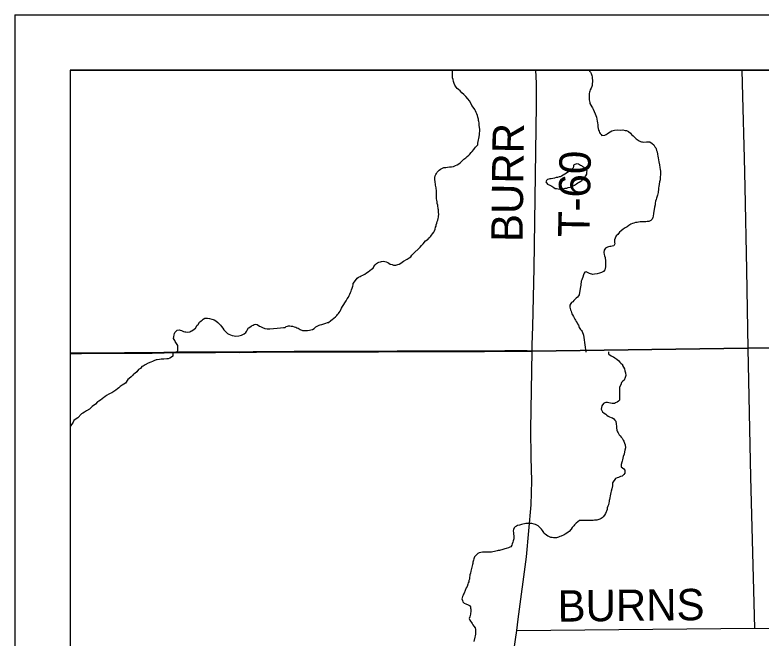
# Model space of a CAD drawing. Extents: x 0 to 34, y 0 to 22.
# Drawn here: x 2 to 3.351, y 19.872 to 21 of the extents above; entities that cross this region are included whole.
import ezdxf

# ---------------------------------------------------------------- set-up
doc = ezdxf.new("R2010")
doc.units = 0
for name, color, linetype in [('GM_X_Corporation', 7, 'Continuous'), ('GM_X_County_Road', 7, 'Continuous'), ('GM_X_Minor_Lake', 7, 'Continuous'), ('GM_X_Minor_River', 7, 'Continuous'), ('GM_X_Township_Road', 7, 'Continuous'), ('GM_X_Township_Road_Text', 7, 'Continuous'), ('SH_Data', 7, 'Continuous')]:
    doc.layers.add(name, color=color, linetype=linetype)

msp = doc.modelspace()

# ---------------------------------------------------------------- linework, layer by layer
at = {"layer": 'GM_X_Corporation'}
for points in [[(6.9799, 20.9), (2.1, 20.9), (2.1, 20.3879), (2.1205, 20.3882), (2.1982, 20.3886), (2.2479, 20.3887), (2.2915, 20.3895), (2.3257, 20.3896), (2.363, 20.39), (2.3847, 20.39), (2.4065, 20.39), (2.4312, 20.3904), (2.4374, 20.3905), (2.4684, 20.3906), (2.5057, 20.3907), (2.515, 20.3907), (2.5336, 20.3908), (2.5492, 20.3908), (2.5709, 20.3908), (2.5926, 20.3909), (2.6268, 20.391), (2.6578, 20.3911), (2.6919, 20.3913), (2.7071, 20.3914), (2.7505, 20.3915), (2.7629, 20.3915), (2.8126, 20.3916), (2.8375, 20.3917), (2.8499, 20.3918), (2.8623, 20.3918), (2.887, 20.3922), (2.9019, 20.3922), (2.9179, 20.3921), (2.9272, 20.392), (2.9362, 20.3918), (3.3271, 20.397), (4.0334, 20.4012)], [(6.9799, 20.9), (2.1, 20.9), (2.1, 20.3879), (2.1205, 20.3882), (2.1982, 20.3886), (2.2479, 20.3887), (2.2915, 20.3895), (2.3257, 20.3896), (2.363, 20.39), (2.3847, 20.39), (2.4065, 20.39), (2.4312, 20.3904), (2.4374, 20.3905), (2.4684, 20.3906), (2.5057, 20.3907), (2.515, 20.3907), (2.5336, 20.3908), (2.5492, 20.3908), (2.5709, 20.3908), (2.5926, 20.3909), (2.6268, 20.391), (2.6578, 20.3911), (2.6919, 20.3913), (2.7071, 20.3914), (2.7505, 20.3915), (2.7629, 20.3915), (2.8126, 20.3916), (2.8375, 20.3917), (2.8499, 20.3918), (2.8623, 20.3918), (2.887, 20.3922), (2.9019, 20.3922), (2.9179, 20.3921), (2.9272, 20.392), (2.9362, 20.3918), (3.3271, 20.397), (4.0334, 20.4012)], [(4.0334, 20.4012), (3.3271, 20.397), (2.9362, 20.3918), (2.9272, 20.392), (2.9179, 20.3921), (2.9019, 20.3922), (2.887, 20.3922), (2.8623, 20.3918), (2.8499, 20.3918), (2.8375, 20.3917), (2.8126, 20.3916), (2.7629, 20.3915), (2.7505, 20.3915), (2.7071, 20.3914), (2.6919, 20.3913), (2.6578, 20.3911), (2.6268, 20.391), (2.5926, 20.3909), (2.5709, 20.3908), (2.5492, 20.3908), (2.5336, 20.3908), (2.515, 20.3907), (2.5057, 20.3907), (2.4684, 20.3906), (2.4374, 20.3905), (2.4312, 20.3904), (2.4065, 20.39), (2.3847, 20.39), (2.363, 20.39), (2.3257, 20.3896), (2.2915, 20.3895), (2.2479, 20.3887), (2.1982, 20.3886), (2.1205, 20.3882), (2.1, 20.3879), (2.1, 14.1)], [(4.0334, 20.4012), (3.3271, 20.397), (2.9362, 20.3918), (2.9272, 20.392), (2.9179, 20.3921), (2.9019, 20.3922), (2.887, 20.3922), (2.8623, 20.3918), (2.8499, 20.3918), (2.8375, 20.3917), (2.8126, 20.3916), (2.7629, 20.3915), (2.7505, 20.3915), (2.7071, 20.3914), (2.6919, 20.3913), (2.6578, 20.3911), (2.6268, 20.391), (2.5926, 20.3909), (2.5709, 20.3908), (2.5492, 20.3908), (2.5336, 20.3908), (2.515, 20.3907), (2.5057, 20.3907), (2.4684, 20.3906), (2.4374, 20.3905), (2.4312, 20.3904), (2.4065, 20.39), (2.3847, 20.39), (2.363, 20.39), (2.3257, 20.3896), (2.2915, 20.3895), (2.2479, 20.3887), (2.1982, 20.3886), (2.1205, 20.3882), (2.1, 20.3879), (2.1, 15.3574)]]:
    msp.add_lwpolyline(points, dxfattribs=at)
at = {"layer": 'GM_X_County_Road'}
msp.add_lwpolyline([(3.3273, 20.3964), (3.3254, 20.5388), (3.322, 20.6881), (3.3208, 20.7409), (3.318, 20.8528), (3.3167, 20.9)], dxfattribs=at)
at = {"layer": 'GM_X_Minor_Lake'}
for points in [[(2.9643, 20.6937), (2.9685, 20.6918), (2.9719, 20.69), (2.9754, 20.6877), (2.9784, 20.6862), (2.9807, 20.6859), (2.9834, 20.6851), (2.9868, 20.6848), (2.9898, 20.6848), (2.9921, 20.6852), (2.9963, 20.6864), (2.999, 20.6868), (3.0016, 20.6876), (3.0054, 20.6884), (3.0077, 20.6892), (3.0103, 20.6908), (3.013, 20.6919), (3.0167, 20.6946), (3.0194, 20.6962), (3.0217, 20.6973), (3.0243, 20.6989), (3.0262, 20.7004), (3.0303, 20.7043), (3.0318, 20.7062), (3.0337, 20.7089), (3.0352, 20.7116), (3.0355, 20.7154), (3.0359, 20.718), (3.0344, 20.7199), (3.032, 20.7226), (3.0301, 20.7237), (3.0282, 20.7252), (3.0263, 20.7267), (3.024, 20.7278), (3.0221, 20.7289), (3.0202, 20.7301), (3.0175, 20.7304), (3.0156, 20.73), (3.0137, 20.7292), (3.0115, 20.7281), (3.0111, 20.7258), (3.0104, 20.7231), (3.0085, 20.7212), (3.0058, 20.7192), (3.0036, 20.7166), (3.0013, 20.7154), (2.9988, 20.7134)], [(2.9988, 20.7134), (2.9896, 20.7084), (2.987, 20.7073), (2.9851, 20.7069), (2.9824, 20.7061), (2.9798, 20.7057), (2.9771, 20.7049), (2.9737, 20.7041), (2.9707, 20.7037), (2.9684, 20.7033), (2.9665, 20.7029), (2.9642, 20.7025), (2.9623, 20.7005), (2.9612, 20.6979), (2.9643, 20.6937)]]:
    msp.add_lwpolyline(points, dxfattribs=at)
at = {"layer": 'GM_X_Minor_River'}
msp.add_line((2.7923, 20.8997), (2.7923, 20.9), dxfattribs=at)
for points in [[(2.7668, 20.6338), (2.7668, 20.6361), (2.7672, 20.6391), (2.7671, 20.6429), (2.7667, 20.6452), (2.7667, 20.6471), (2.7663, 20.649), (2.7663, 20.6509), (2.7659, 20.6532), (2.7655, 20.6559), (2.7647, 20.6589), (2.7643, 20.6619), (2.7639, 20.6646), (2.7635, 20.6672), (2.7634, 20.6707), (2.7634, 20.6737), (2.7634, 20.6768), (2.7633, 20.6798), (2.7633, 20.6828), (2.7629, 20.6851), (2.7625, 20.6874), (2.7621, 20.6893), (2.7617, 20.692), (2.7613, 20.6942), (2.7609, 20.6969), (2.7601, 20.7034), (2.7604, 20.706), (2.7608, 20.7087), (2.7619, 20.7114), (2.763, 20.7133), (2.7645, 20.7152), (2.766, 20.7175), (2.7679, 20.719), (2.7705, 20.721), (2.7743, 20.7229), (2.7766, 20.7237), (2.78, 20.7241), (2.7834, 20.7245), (2.7868, 20.725), (2.7906, 20.7254), (2.7941, 20.7258), (2.7978, 20.7274), (2.8005, 20.7289), (2.8035, 20.7308), (2.8065, 20.7331), (2.8095, 20.7358), (2.8129, 20.7389), (2.8163, 20.7416), (2.819, 20.7439), (2.8216, 20.7462), (2.8235, 20.7478), (2.8261, 20.7512), (2.828, 20.7528), (2.8306, 20.7562), (2.8321, 20.7585), (2.834, 20.7608), (2.8355, 20.7628), (2.8378, 20.7651), (2.8381, 20.7677), (2.8385, 20.7712), (2.8392, 20.7742), (2.8399, 20.7761), (2.8414, 20.783), (2.8413, 20.786), (2.8417, 20.7895), (2.8417, 20.7925), (2.8412, 20.7967), (2.8408, 20.7997), (2.8404, 20.8024), (2.8404, 20.805), (2.84, 20.8073), (2.8396, 20.8092), (2.8392, 20.8111), (2.838, 20.8153), (2.8376, 20.8183), (2.8364, 20.821), (2.8353, 20.8236), (2.8337, 20.8267), (2.8326, 20.8289), (2.8298, 20.8331), (2.8275, 20.8361), (2.8252, 20.8403), (2.8229, 20.8444), (2.8198, 20.8482), (2.8164, 20.8524), (2.8129, 20.8561), (2.8094, 20.8591), (2.806, 20.8629), (2.8029, 20.8652), (2.8006, 20.867), (2.7991, 20.8693), (2.7964, 20.8731), (2.7952, 20.8761), (2.794, 20.8795), (2.7932, 20.8829), (2.7924, 20.886), (2.7924, 20.8886), (2.792, 20.8909), (2.7924, 20.8936), (2.7923, 20.8962), (2.7923, 20.8997)], [(3.0394, 20.9), (3.0405, 20.8985), (3.0421, 20.8966), (3.0432, 20.8943), (3.0444, 20.8905), (3.0448, 20.8878), (3.0452, 20.8848), (3.0457, 20.8818), (3.0457, 20.8787), (3.0453, 20.8761), (3.045, 20.8726), (3.0442, 20.8703), (3.0431, 20.8677), (3.0416, 20.8646), (3.0409, 20.8623), (3.0402, 20.86), (3.0394, 20.8577), (3.0395, 20.8554), (3.0395, 20.8528), (3.0395, 20.8494), (3.0399, 20.8463), (3.0403, 20.844), (3.0407, 20.8418), (3.0411, 20.8395), (3.0427, 20.8365), (3.0446, 20.8338), (3.0454, 20.8319), (3.0466, 20.8293), (3.0504, 20.8209), (3.052, 20.8179), (3.0528, 20.8149), (3.0536, 20.8111), (3.054, 20.808), (3.0548, 20.8046), (3.0552, 20.8012), (3.0556, 20.7978), (3.056, 20.7947), (3.0568, 20.7917), (3.0576, 20.7894), (3.0584, 20.7875), (3.0595, 20.7856), (3.0611, 20.7838), (3.0626, 20.7819), (3.0679, 20.7823), (3.0702, 20.7838), (3.0721, 20.785), (3.0747, 20.7869), (3.0774, 20.7885), (3.0804, 20.79), (3.0857, 20.7916), (3.0903, 20.792)], [(3.0903, 20.792), (3.0956, 20.7917), (3.1005, 20.7918), (3.1047, 20.7911), (3.1074, 20.7907), (3.1108, 20.7892), (3.1143, 20.7862), (3.1166, 20.7836), (3.1196, 20.7813), (3.1212, 20.7794), (3.125, 20.776), (3.1281, 20.7734), (3.13, 20.7723), (3.1323, 20.7712), (3.1342, 20.7704), (3.1361, 20.7701), (3.1384, 20.7697), (3.1433, 20.7702), (3.1456, 20.7706), (3.1475, 20.7702), (3.1494, 20.7702), (3.1536, 20.7676), (3.1567, 20.765), (3.1586, 20.7616), (3.1602, 20.7593), (3.1609, 20.7574), (3.1617, 20.7547), (3.1625, 20.7521), (3.1633, 20.7479), (3.1641, 20.7445), (3.1645, 20.7415), (3.1653, 20.738), (3.1657, 20.7339), (3.1669, 20.7285), (3.1677, 20.724), (3.1685, 20.7202), (3.1689, 20.7171), (3.169, 20.7145), (3.1686, 20.7111), (3.1683, 20.7065), (3.168, 20.7019), (3.1672, 20.6977), (3.1665, 20.6935), (3.1658, 20.6897), (3.1654, 20.687), (3.1651, 20.6836), (3.1648, 20.6806), (3.1644, 20.6787), (3.164, 20.6764), (3.1633, 20.6737), (3.1626, 20.6718), (3.1618, 20.6687), (3.1607, 20.6661), (3.16, 20.663), (3.1593, 20.6596), (3.1589, 20.6562), (3.1582, 20.652), (3.1564, 20.6405), (3.1557, 20.636), (3.155, 20.6337), (3.1535, 20.6306), (3.1516, 20.6283), (3.1478, 20.6264), (3.1448, 20.6263), (3.1425, 20.6259), (3.1398, 20.6259), (3.1372, 20.6259), (3.1345, 20.6258), (3.1322, 20.6254), (3.1292, 20.625), (3.1265, 20.6246), (3.1235, 20.6242), (3.1205, 20.623), (3.1182, 20.6226), (3.1152, 20.6215), (3.1114, 20.6187), (3.1084, 20.6164), (3.105, 20.6145), (3.1012, 20.6122), (3.0974, 20.6095), (3.0944, 20.6068), (3.0914, 20.6029), (3.0888, 20.6002), (3.0865, 20.596), (3.0858, 20.593), (3.0854, 20.5903), (3.0855, 20.588), (3.0863, 20.5858), (3.0844, 20.5819), (3.0814, 20.5815), (3.0791, 20.5811), (3.0772, 20.5807), (3.0745, 20.5803), (3.0726, 20.5799), (3.0692, 20.578), (3.0666, 20.5741), (3.0663, 20.5699), (3.0667, 20.5665), (3.0675, 20.5643), (3.0686, 20.5612), (3.0687, 20.5593)], [(2.5298, 20.4289), (2.5332, 20.4293), (2.5359, 20.4301), (2.5389, 20.4305), (2.5415, 20.4328), (2.5449, 20.4355), (2.5472, 20.4371), (2.5506, 20.4386), (2.5525, 20.439), (2.5555, 20.4398), (2.5593, 20.441), (2.5631, 20.4425), (2.5658, 20.4433), (2.5677, 20.4437), (2.5718, 20.4468), (2.5744, 20.4491), (2.5771, 20.4514), (2.5801, 20.4538), (2.5827, 20.4561), (2.5842, 20.458), (2.5857, 20.4599), (2.5872, 20.4618), (2.5887, 20.4641), (2.5902, 20.4664), (2.5913, 20.4691), (2.5932, 20.4725), (2.5955, 20.476), (2.5973, 20.4791), (2.5996, 20.4825), (2.6018, 20.4863), (2.6037, 20.4894), (2.6052, 20.4925), (2.6063, 20.4947), (2.6074, 20.4978), (2.6089, 20.5001), (2.6096, 20.5024), (2.6107, 20.5058), (2.6115, 20.5093), (2.6122, 20.5119), (2.6126, 20.5138), (2.6182, 20.5219), (2.6197, 20.5238), (2.6223, 20.5257), (2.625, 20.5265), (2.6269, 20.5277), (2.6299, 20.5292), (2.6333, 20.5312), (2.6363, 20.5331), (2.6397, 20.5354), (2.6424, 20.5374), (2.6454, 20.5397), (2.6484, 20.542), (2.6499, 20.5447), (2.6521, 20.5477), (2.6544, 20.55), (2.6567, 20.5516), (2.6589, 20.5528), (2.6616, 20.5535), (2.6639, 20.554), (2.6669, 20.5544), (2.6696, 20.554), (2.6722, 20.5533), (2.6749, 20.5518), (2.6768, 20.5507), (2.6795, 20.5492), (2.6829, 20.5481), (2.6852, 20.5473), (2.6871, 20.5473), (2.6894, 20.5474), (2.6932, 20.5486), (2.6958, 20.5493), (2.6989, 20.5509), (2.7038, 20.5544), (2.7102, 20.5582), (2.714, 20.5602), (2.7166, 20.5625), (2.7185, 20.5652), (2.7211, 20.5675), (2.723, 20.5698), (2.7313, 20.5771), (2.7336, 20.5798), (2.7362, 20.5825), (2.7392, 20.5856), (2.7433, 20.5913), (2.7479, 20.594), (2.7486, 20.5959), (2.7512, 20.5979), (2.7531, 20.5994), (2.7542, 20.6013), (2.7561, 20.604), (2.7584, 20.6071), (2.7595, 20.6094), (2.7606, 20.6124), (2.7613, 20.6159), (2.7624, 20.6178), (2.7628, 20.6204), (2.7639, 20.6231), (2.7646, 20.6262), (2.7658, 20.6288), (2.7665, 20.6315), (2.7668, 20.6338)], [(3.0687, 20.5593), (3.0691, 20.5563), (3.0691, 20.5521), (3.0691, 20.5479), (3.0692, 20.5441), (3.0688, 20.5411), (3.0681, 20.5388), (3.0655, 20.5357), (3.0621, 20.5338), (3.0583, 20.5326), (3.0541, 20.5314), (3.0495, 20.531), (3.0465, 20.5305), (3.0442, 20.5309), (3.0423, 20.5313), (3.0404, 20.5324), (3.0366, 20.5342), (3.0343, 20.535), (3.0316, 20.5346), (3.0309, 20.5327), (3.0294, 20.5296), (3.0279, 20.5254), (3.0268, 20.5227), (3.0261, 20.5204), (3.0253, 20.5185), (3.025, 20.5162), (3.0246, 20.5136), (3.0243, 20.5113), (3.0239, 20.5079), (3.0221, 20.4979), (3.0214, 20.4938), (3.0203, 20.4918), (3.0184, 20.4892), (3.0162, 20.4872), (3.0139, 20.4853), (3.0116, 20.483), (3.0098, 20.4811), (3.0079, 20.4795), (3.0064, 20.4776), (3.0045, 20.4746), (3.0045, 20.4711), (3.0057, 20.4662), (3.0069, 20.4639), (3.0077, 20.4616), (3.0085, 20.4594), (3.0096, 20.4571), (3.0112, 20.4541), (3.0123, 20.4518), (3.0135, 20.4495), (3.015, 20.4476), (3.0162, 20.4454), (3.0181, 20.4427), (3.0185, 20.4408), (3.0201, 20.4389), (3.0216, 20.4344), (3.0239, 20.431), (3.0259, 20.4291), (3.027, 20.4272), (3.0294, 20.4204), (3.0302, 20.4166), (3.0337, 20.3899)], [(2.2945, 20.3879), (2.2952, 20.3956), (2.2952, 20.399), (2.2948, 20.4017), (2.294, 20.4036), (2.2913, 20.407), (2.2901, 20.4089), (2.2893, 20.4108), (2.2874, 20.4146), (2.2878, 20.4176), (2.2881, 20.421), (2.2892, 20.4233), (2.2896, 20.4252), (2.2918, 20.4279), (2.2937, 20.4295), (2.2971, 20.4299), (2.299, 20.4295), (2.3017, 20.4288), (2.3055, 20.4273), (2.3074, 20.4266), (2.3093, 20.4266), (2.312, 20.4262), (2.3166, 20.4267), (2.3184, 20.4278), (2.3203, 20.4282), (2.3245, 20.4313), (2.3268, 20.4329), (2.3301, 20.4386), (2.332, 20.4401), (2.3342, 20.4443), (2.3369, 20.4463), (2.3388, 20.4474), (2.341, 20.4494), (2.3437, 20.4513), (2.3486, 20.4513), (2.3524, 20.4506), (2.3566, 20.4495), (2.3589, 20.4488), (2.3608, 20.448), (2.3639, 20.4466), (2.3673, 20.4432), (2.3696, 20.4413), (2.3719, 20.4386), (2.3742, 20.436), (2.3766, 20.4334), (2.3785, 20.4303), (2.38, 20.4285), (2.3831, 20.4251), (2.385, 20.4236), (2.3873, 20.4224), (2.39, 20.4213), (2.3934, 20.4202), (2.3968, 20.4191), (2.3995, 20.4188), (2.4056, 20.4192), (2.4079, 20.42), (2.4105, 20.4208), (2.4124, 20.4216), (2.415, 20.4231), (2.4181, 20.4254), (2.4192, 20.4273), (2.4207, 20.4296), (2.4229, 20.4335), (2.4248, 20.4346), (2.4282, 20.4373), (2.4312, 20.4389), (2.4331, 20.4397), (2.4354, 20.4405), (2.4388, 20.4397), (2.4427, 20.4371), (2.4446, 20.436), (2.448, 20.4341), (2.4522, 20.4323), (2.4564, 20.4319), (2.4617, 20.432), (2.4682, 20.4324), (2.4746, 20.4329), (2.4807, 20.4337), (2.486, 20.4341), (2.4891, 20.4345), (2.4909, 20.4361), (2.4936, 20.4369), (2.4955, 20.4373), (2.4978, 20.4373), (2.5001, 20.4369), (2.5027, 20.4366), (2.5058, 20.4359), (2.5084, 20.4347), (2.5104, 20.434), (2.5126, 20.4329), (2.5146, 20.4321), (2.5165, 20.431), (2.5207, 20.4292), (2.5233, 20.4288), (2.5267, 20.4288), (2.5298, 20.4289)], [(2.2859, 20.3879), (2.2859, 20.3825), (2.2836, 20.381), (2.2802, 20.3787), (2.2775, 20.3779), (2.2748, 20.3776), (2.2695, 20.3772), (2.2672, 20.3768), (2.2646, 20.3768), (2.2615, 20.3764), (2.2577, 20.3757), (2.2558, 20.3757), (2.2517, 20.3738), (2.249, 20.373), (2.246, 20.3715), (2.241, 20.37), (2.2357, 20.3666), (2.2319, 20.3643), (2.2296, 20.3639), (2.2273, 20.3605), (2.2239, 20.3582), (2.2209, 20.3544), (2.2171, 20.351), (2.2144, 20.3502), (2.2136, 20.3479), (2.2102, 20.3449), (2.2068, 20.3422), (2.2045, 20.3404), (2.1999, 20.3335), (2.1942, 20.3301), (2.1908, 20.3278), (2.1882, 20.3255), (2.1859, 20.3236), (2.1828, 20.321), (2.179, 20.3183), (2.1756, 20.3164), (2.1726, 20.3149), (2.1703, 20.3138), (2.1661, 20.3111), (2.1627, 20.3092), (2.1608, 20.3077), (2.1581, 20.3054), (2.1551, 20.3031), (2.152, 20.3008), (2.1494, 20.2997), (2.1456, 20.2955), (2.1399, 20.2913), (2.1349, 20.2868), (2.1296, 20.2837), (2.1258, 20.2811), (2.1227, 20.2796), (2.1208, 20.2784), (2.1136, 20.2712), (2.1091, 20.2678), (2.1064, 20.2659), (2.1056, 20.2628), (2.1003, 20.2552), (2.1, 20.2549)], [(3.0747, 20.3901), (3.0747, 20.3868), (3.0755, 20.3864), (3.0797, 20.3834), (3.0819, 20.3818), (3.0838, 20.3811), (3.0861, 20.3796), (3.0895, 20.3769), (3.0933, 20.3738), (3.0952, 20.3719), (3.0971, 20.3697), (3.0998, 20.3674), (3.1002, 20.3655), (3.1017, 20.3628), (3.1036, 20.3598), (3.1043, 20.356), (3.1055, 20.3525), (3.1058, 20.3476), (3.1047, 20.3438), (3.1028, 20.3389), (3.1009, 20.3373), (3.0982, 20.3351), (3.0967, 20.3309), (3.0948, 20.3267), (3.0944, 20.3198), (3.0948, 20.3164), (3.0948, 20.3107), (3.0948, 20.3069), (3.0944, 20.3027), (3.0925, 20.3008), (3.0902, 20.2993), (3.0875, 20.2982), (3.0856, 20.297), (3.0837, 20.2966), (3.0811, 20.2967), (3.0784, 20.2974), (3.0754, 20.2982), (3.0727, 20.2986), (3.0701, 20.2986), (3.0678, 20.2978), (3.0655, 20.297), (3.0628, 20.2925), (3.0613, 20.2864), (3.0624, 20.2841), (3.064, 20.2818), (3.067, 20.2792), (3.0697, 20.2773), (3.0716, 20.2757), (3.0738, 20.2742), (3.0765, 20.2727), (3.0792, 20.2716), (3.0818, 20.2708), (3.0841, 20.2689), (3.0864, 20.267), (3.0879, 20.2647), (3.0886, 20.2594), (3.089, 20.2556), (3.089, 20.2529), (3.0898, 20.2487), (3.0909, 20.2457), (3.092, 20.2438), (3.0939, 20.2404), (3.0955, 20.2385), (3.0974, 20.2358), (3.0993, 20.2339), (3.1011, 20.2308), (3.1027, 20.2289), (3.1038, 20.2248), (3.1046, 20.2221), (3.1053, 20.2164), (3.1045, 20.2122), (3.1038, 20.2095), (3.103, 20.205), (3.1015, 20.2008), (3.1007, 20.1981), (3.1003, 20.1947), (3.0996, 20.1924), (3.0988, 20.1905), (3.0973, 20.1863), (3.0977, 20.1825), (3.1, 20.1803), (3.1022, 20.1787), (3.1045, 20.1765), (3.1045, 20.1711), (3.1026, 20.1681), (3.0992, 20.1654), (3.0961, 20.1647), (3.0927, 20.1631), (3.0901, 20.1624), (3.0874, 20.1609), (3.0821, 20.1536), (3.0821, 20.1476), (3.0805, 20.1426), (3.0794, 20.1384), (3.079, 20.1358), (3.0779, 20.1297), (3.0771, 20.1263), (3.0763, 20.1232), (3.076, 20.1213), (3.0756, 20.1194), (3.0752, 20.1171)], [(3.0752, 20.1171), (3.0744, 20.1137), (3.0737, 20.1111), (3.0725, 20.108), (3.0721, 20.105), (3.0695, 20.0978), (3.0672, 20.0947), (3.0653, 20.0917), (3.0634, 20.0902), (3.0615, 20.0886), (3.0592, 20.0875), (3.0535, 20.086), (3.0516, 20.086), (3.0493, 20.0856), (3.047, 20.0852), (3.0451, 20.0852), (3.0425, 20.0852), (3.0391, 20.0852), (3.0372, 20.0852), (3.0353, 20.0852), (3.0334, 20.0852), (3.0307, 20.0852), (3.0273, 20.0852), (3.025, 20.0852), (3.022, 20.0849), (3.0193, 20.083), (3.0159, 20.0803), (3.0132, 20.0776), (3.0117, 20.0754), (3.009, 20.0723), (3.0071, 20.0693), (3.0037, 20.0651), (3.0018, 20.064), (2.9991, 20.0621), (2.9965, 20.0602), (2.9942, 20.059), (2.9889, 20.0567), (2.9866, 20.056), (2.9839, 20.0548), (2.9805, 20.0537), (2.9775, 20.0537), (2.9748, 20.0537), (2.9725, 20.0541), (2.9702, 20.0545), (2.9668, 20.056), (2.9649, 20.0571), (2.9627, 20.0587), (2.96, 20.0606), (2.9581, 20.0617), (2.9573, 20.0636), (2.9551, 20.067), (2.9532, 20.0693), (2.9513, 20.0712), (2.9494, 20.0735), (2.9471, 20.0754), (2.9448, 20.0769), (2.9422, 20.0777), (2.9399, 20.0785), (2.9361, 20.0796), (2.9273, 20.08), (2.9247, 20.0796), (2.9228, 20.0792), (2.9197, 20.0785), (2.9171, 20.0777), (2.9152, 20.0773), (2.9133, 20.077), (2.9102, 20.0762), (2.908, 20.0751), (2.9057, 20.0735), (2.9038, 20.072), (2.9026, 20.0686), (2.9022, 20.0663), (2.9026, 20.0629), (2.9026, 20.0602), (2.903, 20.0576), (2.903, 20.0545), (2.903, 20.0519), (2.9022, 20.0481), (2.9015, 20.0462), (2.9003, 20.0431), (2.8996, 20.0405), (2.8977, 20.0378), (2.8958, 20.0367), (2.8935, 20.0359), (2.8893, 20.0344), (2.887, 20.0336), (2.8851, 20.0332), (2.8832, 20.0329), (2.8813, 20.0321), (2.8794, 20.0317), (2.8771, 20.031), (2.8752, 20.0306), (2.8733, 20.0302), (2.8707, 20.0295), (2.8684, 20.0291), (2.865, 20.0283), (2.8627, 20.0279), (2.8589, 20.0279), (2.857, 20.0276), (2.8543, 20.0276), (2.8513, 20.0276)], [(2.8513, 20.0276), (2.8494, 20.0276), (2.8463, 20.0276), (2.8433, 20.0272), (2.8403, 20.0268), (2.838, 20.0253), (2.8361, 20.0238), (2.8338, 20.0215), (2.8323, 20.0192), (2.8311, 20.0158), (2.8304, 20.0131), (2.8292, 20.0097), (2.8288, 20.0074), (2.8285, 20.0055), (2.8281, 20.0033), (2.8254, 19.9934), (2.8246, 19.9899), (2.8239, 19.9869), (2.8235, 19.985), (2.8231, 19.9827), (2.8231, 19.9793), (2.822, 19.9763), (2.8216, 19.974), (2.8204, 19.9721), (2.8197, 19.9698), (2.8185, 19.9656), (2.817, 19.9633), (2.8151, 19.9584), (2.8132, 19.9538), (2.8121, 19.9519), (2.8117, 19.95), (2.8105, 19.9477), (2.8098, 19.9455), (2.8094, 19.9436), (2.8102, 19.9405), (2.8109, 19.9378), (2.8136, 19.9356), (2.8162, 19.9344), (2.8208, 19.9325), (2.8231, 19.9314), (2.8246, 19.9287), (2.825, 19.9268), (2.8253, 19.9249), (2.8257, 19.9219), (2.8246, 19.9158), (2.8234, 19.9108), (2.8227, 19.9078), (2.8234, 19.9051), (2.8246, 19.9028), (2.8268, 19.9006), (2.828, 19.8987), (2.8291, 19.8964), (2.8306, 19.8937), (2.8333, 19.8907), (2.8337, 19.888), (2.834, 19.8857), (2.834, 19.8838), (2.8336, 19.8796), (2.8333, 19.8762), (2.8329, 19.8743), (2.831, 19.866)]]:
    msp.add_lwpolyline(points, dxfattribs=at)
at = {"layer": 'GM_X_Township_Road'}
msp.add_line((2.9089, 19.8864), (3.3398, 19.8904), dxfattribs=at)
for points in [[(2.9364, 20.3913), (2.9367, 20.4026), (2.9372, 20.4197), (2.9375, 20.436), (2.9402, 20.5415), (2.9443, 20.8365), (2.9441, 20.8768), (2.943, 20.9)], [(2.1, 20.3874), (2.1207, 20.3876), (2.1984, 20.3881), (2.2482, 20.3882), (2.2917, 20.389), (2.3259, 20.389), (2.3632, 20.3894), (2.385, 20.3895), (2.4067, 20.3894), (2.4314, 20.3898), (2.4376, 20.39), (2.4686, 20.3901), (2.5059, 20.3901), (2.5152, 20.3901), (2.5339, 20.3902), (2.5494, 20.3903), (2.5711, 20.3903), (2.5929, 20.3903), (2.627, 20.3905), (2.6581, 20.3906), (2.6922, 20.3908), (2.7073, 20.3908), (2.7507, 20.3909), (2.7631, 20.391), (2.8128, 20.3911), (2.8377, 20.3912), (2.8501, 20.3912), (2.8625, 20.3913), (2.8872, 20.3916), (2.9021, 20.3916), (2.9181, 20.3915), (2.9274, 20.3914), (2.9364, 20.3913)], [(2.9089, 19.8864), (2.9109, 19.9068), (2.9265, 20.0192), (2.9349, 20.1134), (2.9358, 20.1567), (2.9345, 20.1993), (2.9339, 20.2499), (2.9364, 20.3913)], [(3.3398, 19.8904), (3.3325, 20.1636), (3.3273, 20.3964)], [(2.8299, 18.8735), (2.8303, 19.065), (2.8273, 19.3405), (2.8254, 19.51), (2.8254, 19.5256), (2.8278, 19.5381), (2.8424, 19.5943), (2.879, 19.7279), (2.889, 19.7716), (2.8964, 19.8073), (2.903, 19.8491), (2.9089, 19.8864)], [(3.3398, 19.8904), (3.4609, 19.8884), (3.5577, 19.8859), (3.587, 19.8777)]]:
    msp.add_lwpolyline(points, dxfattribs=at)
at = {"layer": 'SH_Data'}
for p, q in [((2, 21), (9, 21)), ((2, 21), (2, 14)), ((2.1, 20.9), (2.1, 14.1)), ((2.1, 20.9), (8.9, 20.9))]:
    msp.add_line(p, q, dxfattribs=at)

# ---------------------------------------------------------------- texts
at = {"layer": 'GM_X_Township_Road_Text'}
for s, rotation, p in [('BURR', 89.2432, (2.919, 20.5888)), ('T-60', 88.9397, (3.04, 20.5975)), ('BURNS', 0.6187, (2.9828, 19.902))]:
    msp.add_text(s, height=0.05682, rotation=rotation, dxfattribs=at).set_placement(p)

doc.saveas('drawing.dxf')
